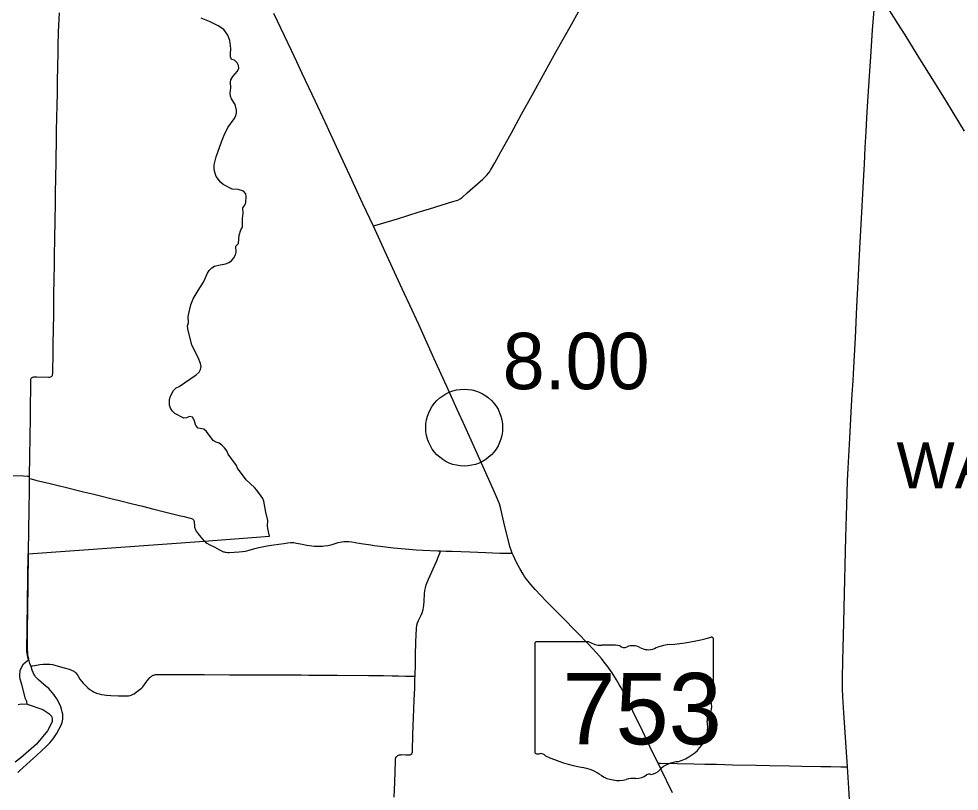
# Model space of a CAD drawing. Extents: x 1597222 to 1925846, y 496284 to 911751.
# Drawn here: x 1709106 to 1727439, y 531911 to 546977 of the extents above; entities that cross this region are included whole.
import ezdxf

# ---------------------------------------------------------------- set-up
doc = ezdxf.new("R2010")
doc.units = 0
for name, color, linetype in [('Default', 7, 'Continuous'), ('GM_X_County_Road', 7, 'Continuous'), ('GM_X_State_Route', 7, 'Continuous'), ('GM_X_State_Shield', 7, 'Continuous'), ('GM_X_Township', 7, 'Continuous'), ('GM_X_Township_Road', 7, 'Continuous'), ('GM_X_Township_Text', 7, 'Continuous')]:
    doc.layers.add(name, color=color, linetype=linetype)

msp = doc.modelspace()

# ---------------------------------------------------------------- linework, layer by layer
at = {"layer": 'Default'}
msp.add_circle((1717789, 539002), 750, dxfattribs=at)
msp.add_circle((1717789, 539002), 750, dxfattribs=at)
at = {"layer": 'GM_X_County_Road'}
for points in [[(1725811, 547514), (1725853, 547471), (1725904, 547410), (1725959, 547329), (1726239, 546886), (1726380, 546662), (1726544, 546398), (1726699, 546147), (1726984, 545687), (1727131, 545450), (1727276, 545212), (1727448, 544933), (1727539, 544783)], [(1725259, 532385), (1725233, 532769), (1725190, 533440), (1725171, 533751), (1725164, 533915), (1725165, 534112), (1725171, 534457), (1725188, 535195), (1725194, 535490), (1725231, 536868), (1725249, 537491), (1725264, 537966), (1725276, 538212), (1725314, 538916), (1725335, 539310), (1725356, 539653), (1725372, 539915), (1725388, 540177), (1725415, 540751), (1725446, 541357), (1725472, 541848), (1725485, 542110), (1725509, 542618), (1725529, 542962), (1725548, 543323), (1725580, 543929), (1725591, 544142), (1725608, 544469), (1725625, 544780), (1725639, 545043), (1725659, 545370), (1725700, 545959), (1725718, 546237), (1725750, 546761), (1725792, 547301)], [(1709316, 538058), (1709317, 538176), (1709320, 538324), (1709323, 538471), (1709328, 538783), (1709330, 538931), (1709333, 539078), (1709337, 539505), (1709339, 539702), (1709338, 539915), (1709340, 539930), (1709343, 539946), (1709349, 539960), (1709357, 539972), (1709368, 539982), (1709381, 539989), (1709396, 539994), (1709412, 539995), (1709428, 539996), (1709461, 539996), (1709691, 539988), (1709708, 539989), (1709725, 539992), (1709741, 539999), (1709754, 540011), (1709762, 540027), (1709766, 540044), (1709768, 540061), (1709769, 540077), (1709770, 540176), (1709773, 540373), (1709777, 540602), (1709783, 540947), (1709786, 541176), (1709790, 541472), (1709792, 541603), (1709797, 541882), (1709801, 542193), (1709804, 542423), (1709808, 542620), (1709810, 542784), (1709813, 542948), (1709814, 543079), (1709820, 543341), (1709824, 543587), (1709828, 543866), (1709832, 544194), (1709842, 544653), (1709844, 544801), (1709849, 545047), (1709855, 545293), (1709858, 545523), (1709861, 545703), (1709869, 546097), (1709872, 546261), (1709876, 546441), (1709883, 546720), (1709897, 547097)], [(1716018, 542933), (1716049, 542943), (1716488, 543078), (1716895, 543205), (1717114, 543272), (1717569, 543411), (1717663, 543442), (1717708, 543465), (1717748, 543494), (1717846, 543582), (1718154, 543852), (1718225, 543921), (1718268, 543971), (1718286, 543997), (1718304, 544026), (1718386, 544169), (1718505, 544384), (1718704, 544743), (1718906, 545118), (1719114, 545491), (1719297, 545820), (1719583, 546337), (1719879, 546867), (1720015, 547111)], [(1708999, 538066), (1709196, 538061), (1709277, 538059), (1709316, 538058)], [(1709296, 536542), (1709298, 536700), (1709300, 536880), (1709304, 537094), (1709307, 537307), (1709313, 537865), (1709315, 538010)], [(1709315, 538010), (1709316, 538058)], [(1709315, 538010), (1709349, 538001), (1709460, 537972), (1709715, 537910), (1709874, 537871), (1710034, 537832), (1710368, 537751), (1710543, 537708), (1710671, 537676), (1710926, 537615), (1711070, 537581), (1711324, 537518), (1711515, 537471), (1711738, 537415), (1712104, 537322), (1712232, 537291), (1712327, 537269), (1712423, 537246), (1712451, 537239), (1712472, 537232), (1712484, 537225), (1712499, 537214), (1712510, 537202), (1712517, 537188), (1712522, 537174), (1712525, 537158), (1712526, 537141), (1712529, 537109), (1712530, 537078), (1712533, 537058), (1712536, 537042), (1712542, 537027), (1712549, 537012), (1712557, 536995), (1712564, 536981), (1712602, 536929), (1712656, 536867), (1712688, 536827), (1712721, 536791), (1712725, 536788)], [(1712725, 536788), (1712747, 536769), (1712774, 536751), (1712831, 536718), (1712925, 536671), (1713021, 536619), (1713057, 536601), (1713095, 536583), (1713110, 536578), (1713127, 536574), (1713143, 536571), (1713176, 536569), (1713210, 536570), (1713402, 536579), (1713468, 536584), (1713517, 536591), (1713549, 536598), (1713597, 536611), (1713708, 536642), (1713787, 536663), (1713850, 536677), (1713947, 536694), (1714078, 536716), (1714271, 536744), (1714353, 536758), (1714401, 536762), (1714436, 536762), (1714470, 536759), (1714517, 536752), (1714596, 536737), (1714724, 536712), (1714821, 536696), (1714871, 536692), (1714934, 536689), (1714995, 536688), (1715029, 536690), (1715063, 536694)], [(1715063, 536694), (1715128, 536706), (1715213, 536726), (1715334, 536760), (1715404, 536775), (1715442, 536781), (1715473, 536783), (1715505, 536783), (1715541, 536781), (1715598, 536774), (1715671, 536762)], [(1715671, 536762), (1715699, 536757), (1715823, 536736), (1715969, 536715), (1716034, 536706), (1716148, 536691), (1716409, 536661), (1716638, 536638), (1716850, 536620), (1716981, 536611), (1717277, 536599), (1717326, 536597)], [(1709277, 534689), (1709275, 534782), (1709275, 534896), (1709277, 535011), (1709279, 535191), (1709282, 535290), (1709282, 535372), (1709285, 535568), (1709289, 535831), (1709289, 535995), (1709290, 536126), (1709295, 536372), (1709296, 536542)], [(1717326, 536597), (1717434, 536594), (1717557, 536590), (1717900, 536577), (1718213, 536566), (1718482, 536555), (1718595, 536554), (1718675, 536555), (1718727, 536557)], [(1709301, 534481), (1709299, 534489), (1709284, 534559), (1709281, 534619), (1709277, 534667), (1709277, 534689)], [(1709345, 534345), (1709324, 534404), (1709301, 534481)], [(1709089, 532276), (1709123, 532311), (1709183, 532367), (1709330, 532498), (1709453, 532606), (1709550, 532695), (1709644, 532786), (1709713, 532857), (1709745, 532894), (1709776, 532933), (1709805, 532973), (1709839, 533029), (1709888, 533115), (1709919, 533173), (1709940, 533218), (1709951, 533249), (1709960, 533281), (1709965, 533314), (1709967, 533347), (1709967, 533380), (1709963, 533413), (1709952, 533462), (1709939, 533510), (1709923, 533557), (1709904, 533602), (1709882, 533647), (1709851, 533704), (1709815, 533759), (1709787, 533800), (1709756, 533839), (1709724, 533876), (1709689, 533911), (1709641, 533956), (1709540, 534040), (1709491, 534083), (1709456, 534117), (1709435, 534142), (1709416, 534168), (1709400, 534196), (1709387, 534225), (1709368, 534272), (1709345, 534345)], [(1725239, 529020), (1725233, 529132), (1725235, 529264), (1725243, 529542), (1725252, 529723), (1725258, 529886), (1725268, 530214), (1725276, 530411), (1725285, 530689), (1725297, 531050), (1725304, 531247), (1725309, 531476), (1725306, 531640), (1725287, 531967), (1725259, 532385)]]:
    msp.add_lwpolyline(points, dxfattribs=at)
at = {"layer": 'GM_X_State_Route'}
msp.add_lwpolyline([(1721850, 531876), (1721621, 532349), (1721569, 532456), (1721463, 532673), (1721264, 533087), (1721077, 533470), (1720919, 533794), (1720887, 533854), (1720850, 533925), (1720813, 533992), (1720760, 534082), (1720671, 534220), (1720577, 534355), (1720539, 534404), (1720467, 534498), (1720371, 534610), (1720214, 534778), (1719983, 535011), (1719696, 535304), (1719397, 535608), (1719171, 535846), (1719086, 535945), (1719006, 536049), (1718968, 536101), (1718941, 536143), (1718872, 536255), (1718810, 536370), (1718777, 536441), (1718750, 536504), (1718727, 536557), (1718712, 536595), (1718682, 536687), (1718637, 536845), (1718578, 537101), (1718502, 537420), (1718475, 537515), (1718441, 537608), (1718382, 537743), (1718125, 538311), (1717924, 538760), (1717768, 539104), (1717653, 539358), (1717451, 539807), (1717199, 540359), (1716902, 541016), (1716732, 541390), (1716622, 541628), (1716284, 542357), (1716120, 542715), (1716018, 542933), (1715815, 543369), (1715560, 543920), (1715338, 544396), (1715076, 544961), (1714888, 545362), (1714631, 545912), (1714527, 546135), (1714422, 546357), (1714079, 547084)], dxfattribs=at)
at = {"layer": 'GM_X_State_Shield'}
for p, q in [((1719168, 534790), (1719168, 532676)), ((1720222, 534826), (1719202, 534826)), ((1722648, 533773), (1722648, 534878)), ((1722648, 533773), (1722648, 533773))]:
    msp.add_line(p, q, dxfattribs=at)
for centre, major_axis, start_param, end_param in [((1719208, 534794), (40.3, 0), 1.712693, 3.28349), ((1720464, 535071), (391, 0), 4.042523, 4.731795), ((1721879, 534180), (743, 0), 1.699011, 2.107814), ((1721409, 537707), (3691, 0), 4.814394, 5.042369), ((1722610, 534883), (38.7, 0), 6.141152, 7.989035), ((1720594, 533639), (1404, 0), 1.404758, 1.657858), ((1720913, 534805), (113, 0), 3.836095, 5.185415), ((1721078, 534561), (235, 0), 0.950623, 2.079405), ((1721381, 534896), (282, 0), 4.081561, 5.145723), ((1722639, 533692), (60, 0), 1.883978, 3.671073), ((1722607, 533769), (41.5, 0), 5.05454, 6.418171), ((1722258, 533552), (360, 0), 5.934695, 6.695948), ((1722787, 533310), (262, 0), 2.387724, 3.262537), ((1721615, 533170), (923, 0), 5.101752, 6.440018), ((1719208, 532672), (40.7, 0), 3.00124, 4.508301), ((1719214, 532888), (310, 0), 4.665946, 4.897461), ((1719278, 532554), (112, 0), 0.519207, 1.627899), ((1720691, 534453), (2665, 0), 4.195997, 4.488961), ((1722005, 532083), (506, 0), 1.647645, 2.488434), ((1719896, 531727), (834, 0), 0.823519, 1.323587), ((1720798, 532544), (529, 0), 4.026481, 4.996735), ((1721143, 532386), (282, 0), 4.691044, 5.507374), ((1721398, 532181), (79.4, 0), 1.147584, 2.315152), ((1721364, 532471), (298, 0), 4.937069, 5.64225), ((1721104, 531813), (435, 0), 1.495662, 1.94098)]:
    msp.add_ellipse(centre, major_axis=major_axis, ratio=0.8, start_param=start_param, end_param=end_param, dxfattribs=at)
at = {"layer": 'GM_X_Township'}
for points in [[(1709267, 533609), (1709260, 533659), (1709234, 533713), (1709168, 533993), (1709133, 534097), (1709126, 534154), (1709132, 534273), (1709199, 534393), (1709294, 534476), (1709276, 534558), (1709264, 534638), (1709287, 536542), (1712723, 536789), (1713991, 536883), (1713959, 537032), (1713956, 537088), (1713959, 537192), (1713921, 537351), (1713882, 537566), (1713862, 537620), (1713746, 537784), (1713701, 537835), (1713536, 537983), (1713371, 538212), (1713351, 538262), (1713188, 538486), (1713160, 538549), (1713115, 538609), (1713062, 538662), (1713010, 538697), (1712952, 538718), (1712898, 538754), (1712768, 538924), (1712715, 538975), (1712603, 538991), (1712557, 539041), (1712523, 539148), (1712495, 539206), (1712431, 539221), (1712373, 539194), (1712321, 539188), (1712149, 539281), (1712094, 539331), (1712061, 539382), (1712041, 539440), (1712043, 539551), (1712061, 539614), (1712123, 539724), (1712176, 539777), (1712230, 539803), (1712566, 540033), (1712622, 540084), (1712651, 540136), (1712660, 540196), (1712651, 540256), (1712600, 540373), (1712481, 540609), (1712403, 540932), (1712397, 540987), (1712414, 541048), (1712409, 541171), (1712431, 541289), (1712460, 541399), (1712508, 541512), (1712602, 541677), (1712708, 541838), (1712785, 542014), (1712817, 542065), (1712868, 542119), (1712923, 542152), (1713031, 542177), (1713144, 542197), (1713200, 542221), (1713253, 542254), (1713297, 542312), (1713328, 542375), (1713341, 542427), (1713338, 542544), (1713391, 542593), (1713401, 542757), (1713435, 542863), (1713465, 542915), (1713465, 543079), (1713479, 543187), (1713476, 543287), (1713513, 543343), (1713533, 543395), (1713541, 543511), (1713530, 543565), (1713484, 543616), (1713380, 543645), (1713264, 543652), (1713093, 543743), (1713041, 543791), (1712955, 543901), (1712922, 544005), (1712915, 544066), (1712917, 544128), (1712957, 544285), (1713057, 544579), (1713109, 544708), (1713179, 544854), (1713303, 545026), (1713338, 545086), (1713353, 545144), (1713353, 545196), (1713327, 545303), (1713254, 545414), (1713231, 545470), (1713227, 545530), (1713241, 545634), (1713234, 545740), (1713239, 545790), (1713276, 545854), (1713371, 545959), (1713394, 546017), (1713388, 546069), (1713363, 546120), (1713311, 546168), (1713256, 546185), (1713236, 546235), (1713231, 546287), (1713238, 546396), (1713222, 546552), (1713181, 546659), (1713103, 546768), (1712991, 546843), (1712822, 546924), (1712662, 546988)], [(1709097, 533603), (1709155, 533618), (1709267, 533609), (1709574, 533507), (1709692, 533427), (1709704, 533414), (1709741, 533372), (1709759, 533322), (1709754, 533262), (1709667, 533091), (1709450, 532825), (1709148, 532560), (1709037, 532476)]]:
    msp.add_lwpolyline(points, dxfattribs=at)
at = {"layer": 'GM_X_Township_Road'}
for points in [[(1716831, 534155), (1716838, 534396), (1716842, 534560), (1716849, 534822), (1716859, 535084), (1716867, 535149), (1716879, 535196), (1716897, 535241), (1716949, 535343), (1716969, 535389), (1716988, 535452), (1717004, 535533), (1717012, 535615), (1717017, 535763), (1717023, 535828), (1717032, 535876), (1717051, 535938), (1717094, 536044), (1717247, 536389), (1717297, 536511), (1717315, 536556), (1717326, 536597)], [(1709345, 534345), (1709374, 534353), (1709422, 534362), (1709519, 534379), (1709584, 534386), (1709633, 534388), (1709714, 534386), (1709763, 534382), (1709811, 534370), (1709873, 534352), (1709989, 534318), (1710088, 534288), (1710123, 534277), (1710148, 534267), (1710168, 534258), (1710182, 534249), (1710193, 534241), (1710205, 534230), (1710216, 534218), (1710236, 534193), (1710254, 534166), (1710299, 534097), (1710328, 534057), (1710360, 534019), (1710407, 533972), (1710455, 533927), (1710493, 533896), (1710534, 533868), (1710563, 533851), (1710593, 533837), (1710624, 533824), (1710671, 533809), (1710719, 533798), (1710768, 533790), (1710817, 533784), (1710899, 533778), (1711047, 533772), (1711145, 533770), (1711211, 533771), (1711244, 533774), (1711277, 533779), (1711294, 533784), (1711309, 533789), (1711324, 533796), (1711339, 533804), (1711353, 533813), (1711394, 533842), (1711447, 533881), (1711498, 533922), (1711510, 533934), (1711522, 533946), (1711543, 533971), (1711571, 534011), (1711609, 534064), (1711639, 534103), (1711661, 534127), (1711673, 534138), (1711685, 534148), (1711698, 534157), (1711712, 534165), (1711727, 534171), (1711741, 534177), (1711757, 534181), (1711772, 534184), (1711788, 534186), (1711820, 534188), (1711902, 534186), (1711968, 534185), (1712050, 534184), (1712165, 534184), (1712263, 534184), (1712493, 534184), (1712723, 534184), (1713215, 534181), (1713675, 534179), (1713905, 534178), (1714102, 534179), (1714200, 534180), (1714348, 534179), (1714479, 534178), (1714610, 534178), (1714758, 534177), (1714889, 534176), (1715086, 534175), (1715316, 534174), (1715923, 534168), (1716218, 534165), (1716383, 534163), (1716507, 534160), (1716645, 534156), (1716727, 534154), (1716793, 534155), (1716831, 534155)], [(1716427, 531792), (1716438, 532087), (1716448, 532498), (1716450, 532528), (1716453, 532546), (1716455, 532555), (1716458, 532564), (1716465, 532578), (1716474, 532590), (1716482, 532598), (1716489, 532603), (1716495, 532607), (1716508, 532614), (1716524, 532619), (1716539, 532622), (1716552, 532623), (1716572, 532624), (1716654, 532621), (1716705, 532620), (1716718, 532621), (1716729, 532622), (1716737, 532623), (1716746, 532626), (1716753, 532630), (1716760, 532635), (1716766, 532641), (1716771, 532648), (1716775, 532657), (1716777, 532665), (1716779, 532675), (1716780, 532691), (1716791, 533019), (1716809, 533511), (1716816, 533691), (1716824, 533921), (1716830, 534101), (1716831, 534155)], [(1721569, 532456), (1721614, 532456), (1721942, 532451), (1722269, 532443), (1722482, 532439), (1722711, 532435), (1723021, 532427), (1723480, 532417), (1723741, 532412), (1724134, 532405), (1724363, 532402), (1724739, 532394), (1724936, 532391), (1725132, 532389), (1725230, 532386), (1725259, 532385)]]:
    msp.add_lwpolyline(points, dxfattribs=at)

# ---------------------------------------------------------------- texts
at = {"layer": 'Default'}
msp.add_text('8.00', height=1100, dxfattribs=at).set_placement((1718539, 539752))
msp.add_text('8.00', height=1100, dxfattribs=at).set_placement((1718539, 539752))
at = {"layer": 'GM_X_State_Shield'}
msp.add_text('753', height=1392.2, dxfattribs=at).set_placement((1719704, 532825))
at = {"layer": 'GM_X_Township_Text'}
msp.add_text('WAYNE', height=900, rotation=0, dxfattribs=at).set_placement((1726217, 537817))

doc.saveas('drawing.dxf')
